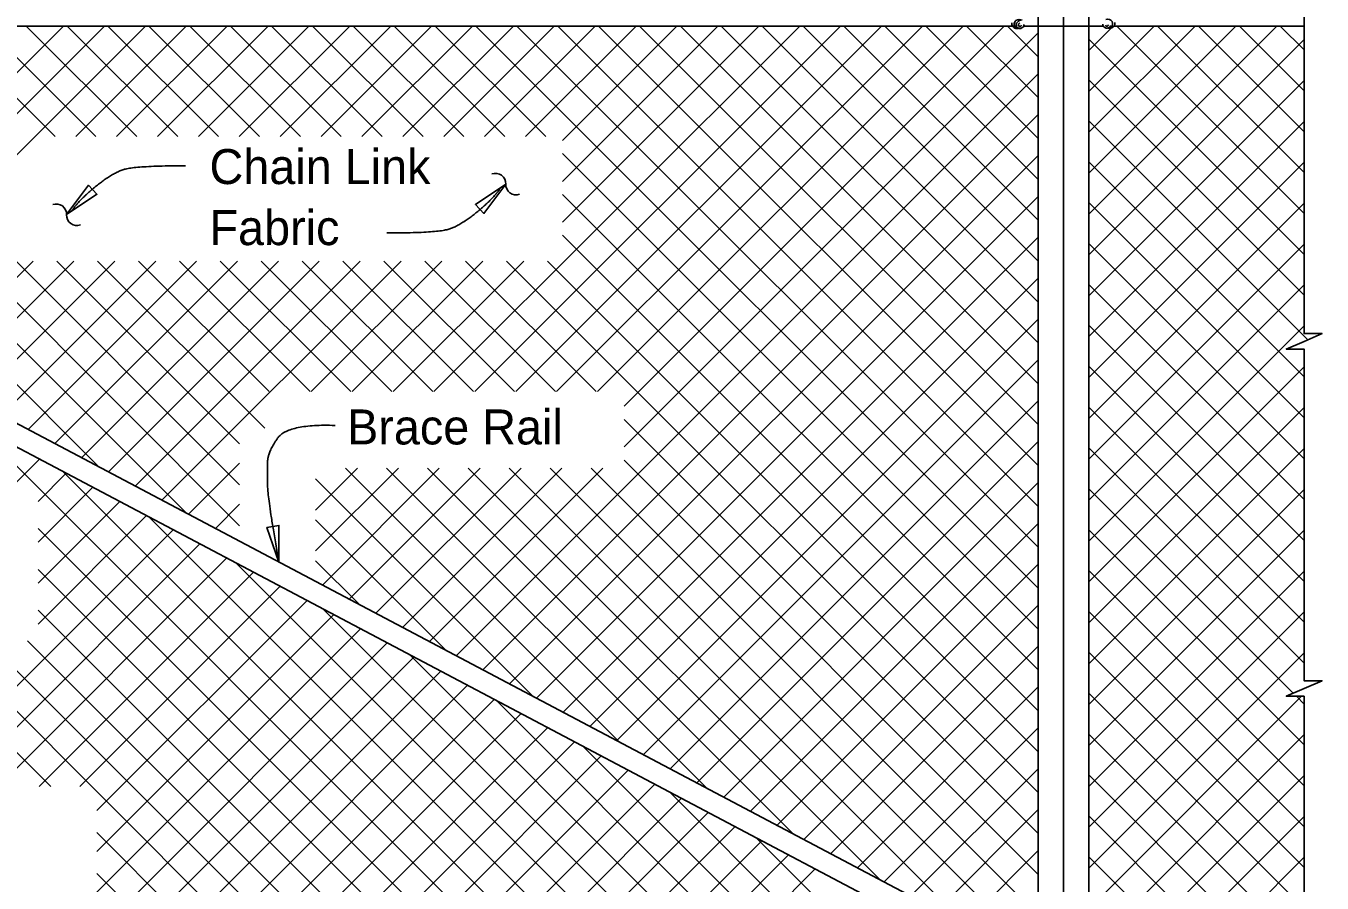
# Model space of a CAD drawing. Extents: x 110698 to 110915, y 110390 to 110472.
# Drawn here: x 110888.85 to 110896.32, y 110461.82 to 110466.76 of the extents above; entities that cross this region are included whole.
import ezdxf

# ---------------------------------------------------------------- set-up
doc = ezdxf.new("R2010")
doc.units = 0
for name, color, linetype in [('AdhocPoint_dp', 7, 'Continuous'), ('Border', 7, 'Continuous'), ('Patterning', 7, 'Continuous'), ('PlotBorder_dp', 7, 'Continuous'), ('SheetBorder_dp', 7, 'Continuous'), ('TextMisc', 7, 'Continuous')]:
    doc.layers.add(name, color=color, linetype=linetype)

msp = doc.modelspace()

# ---------------------------------------------------------------- linework, layer by layer
at = {"layer": 'AdhocPoint_dp'}
msp.add_line((110894.8293, 110469.3136), (110894.8293, 110458.9732), dxfattribs=at)
at = {"layer": 'Patterning'}
msp.add_line((110894.6836, 110466.764), (110894.9752, 110466.764), dxfattribs=at)
at = {"layer": 'PlotBorder_dp'}
for points in [[(110896.2164, 110466.9474), (110896.2164, 110464.9911), (110896.3197, 110464.9911), (110896.2164, 110464.9461), (110896.1131, 110464.9011), (110896.2164, 110464.9011), (110896.2164, 110464.0075)], [(110896.2164, 110464.0075), (110896.2164, 110462.9898), (110896.3197, 110462.9898), (110896.2164, 110462.9448), (110896.1131, 110462.8998), (110896.2164, 110462.8998), (110896.2164, 110460.6954)]]:
    msp.add_lwpolyline(points, dxfattribs=at)
for points in [[(110889.0827, 110465.6766), (110889.2579, 110465.7944), (110889.2093, 110465.8456)], [(110891.6148, 110465.8526), (110891.4396, 110465.7347), (110891.4882, 110465.6836)], [(110890.3071, 110463.6738), (110890.3068, 110463.885), (110890.2373, 110463.8731)]]:
    msp.add_lwpolyline(points, close=True, dxfattribs=at)
for centre, start, end in [((110891.5547, 110465.8554), 357.71778, 109.44499), ((110891.6738, 110465.8507), 177.71778, 289.44499), ((110889.0235, 110465.6785), 357.71778, 109.44499), ((110889.1427, 110465.6737), 177.71778, 289.44499)]:
    msp.add_arc(centre, 0.0596, start, end, dxfattribs=at)
for points in [[(110889.7678, 110465.9582), (110889.4777, 110465.9582), (110889.3411, 110465.9134), (110889.1541, 110465.7598), (110889.1157, 110465.7022)], [(110890.9295, 110465.5709), (110891.2197, 110465.5709), (110891.3563, 110465.6157), (110891.5433, 110465.7693), (110891.5816, 110465.8269)], [(110890.6302, 110464.4616), (110890.3607, 110464.4698), (110890.2426, 110464.3114), (110890.2396, 110464.1902), (110890.2443, 110464.0224), (110890.307, 110463.6737)]]:
    msp.add_open_spline(points, degree=2, dxfattribs=at)
at = {"layer": 'SheetBorder_dp'}
for p, q in [((110886.7285, 110466.764), (110889.2716, 110464.2209)), ((110886.9642, 110466.764), (110889.7714, 110463.9568)), ((110887.1999, 110466.764), (110890.0805, 110463.8834)), ((110887.4356, 110466.764), (110890.0805, 110464.1191)), ((110887.4732, 110465.1713), (110889.0659, 110466.764)), ((110887.6274, 110465.0898), (110889.3016, 110466.764)), ((110887.7816, 110465.0083), (110889.5373, 110466.764)), ((110888.3784, 110466.764), (110889.0161, 110466.1263)), ((110888.6141, 110466.764), (110889.2518, 110466.1263)), ((110888.8498, 110466.764), (110889.4875, 110466.1263)), ((110889.0855, 110466.764), (110889.7232, 110466.1263)), ((110889.1353, 110466.1263), (110889.773, 110466.764)), ((110889.3213, 110466.764), (110889.9589, 110466.1263)), ((110889.371, 110466.1263), (110890.0087, 110466.764)), ((110889.557, 110466.764), (110890.1946, 110466.1263)), ((110889.6067, 110466.1263), (110890.2444, 110466.764)), ((110889.7927, 110466.764), (110890.4303, 110466.1263)), ((110889.8424, 110466.1263), (110890.4801, 110466.764)), ((110890.0284, 110466.764), (110890.666, 110466.1263)), ((110890.0781, 110466.1263), (110890.7158, 110466.764)), ((110890.2641, 110466.764), (110890.9017, 110466.1263)), ((110890.3138, 110466.1263), (110890.9515, 110466.764)), ((110890.4998, 110466.764), (110891.1374, 110466.1263)), ((110890.5495, 110466.1263), (110891.1872, 110466.764)), ((110890.7355, 110466.764), (110891.3731, 110466.1263)), ((110890.7852, 110466.1263), (110891.4229, 110466.764)), ((110890.9712, 110466.764), (110891.6088, 110466.1263)), ((110891.0209, 110466.1263), (110891.6586, 110466.764)), ((110891.2006, 110464.6561), (110893.3085, 110466.764)), ((110891.2069, 110466.764), (110891.8445, 110466.1263)), ((110891.2566, 110466.1263), (110891.8943, 110466.764)), ((110891.4363, 110464.6561), (110893.5442, 110466.764)), ((110891.4426, 110466.764), (110894.6836, 110463.523)), ((110891.4923, 110466.1263), (110892.13, 110466.764)), ((110891.672, 110464.6561), (110893.7799, 110466.764)), ((110891.6783, 110466.764), (110894.6836, 110463.7587)), ((110891.728, 110466.1263), (110892.3657, 110466.764)), ((110891.9077, 110464.6561), (110894.0156, 110466.764)), ((110891.914, 110466.764), (110894.6836, 110463.9944)), ((110891.9415, 110466.1041), (110892.6014, 110466.764)), ((110891.9415, 110465.6327), (110893.0728, 110466.764)), ((110891.9415, 110465.8684), (110892.8371, 110466.764)), ((110892.1434, 110464.6561), (110894.2513, 110466.764)), ((110892.1434, 110464.6561), (110894.2513, 110466.764)), ((110892.1497, 110466.764), (110894.6836, 110464.2301)), ((110892.2962, 110464.5732), (110894.487, 110466.764)), ((110892.2962, 110464.3375), (110894.6836, 110466.7248)), ((110892.3854, 110466.764), (110894.6836, 110464.4658)), ((110892.6211, 110466.764), (110894.6836, 110464.7015)), ((110892.8568, 110466.764), (110894.6836, 110464.9372)), ((110893.0925, 110466.764), (110894.6836, 110465.1729)), ((110893.3282, 110466.764), (110894.6836, 110465.4086)), ((110893.5639, 110466.764), (110894.6836, 110465.6443)), ((110893.7996, 110466.764), (110894.6836, 110465.88)), ((110894.0353, 110466.764), (110894.6836, 110466.1157)), ((110894.271, 110466.764), (110894.6836, 110466.3514)), ((110894.5067, 110466.764), (110894.6836, 110466.5871)), ((110894.9752, 110465.6803), (110896.0589, 110466.764)), ((110894.9752, 110466.1517), (110895.5875, 110466.764)), ((110894.9752, 110466.3874), (110895.3518, 110466.764)), ((110894.9752, 110466.6231), (110895.1047, 110466.7526)), ((110894.9797, 110465.9204), (110895.8232, 110466.764)), ((110895.1358, 110466.764), (110896.2163, 110465.6834)), ((110895.3715, 110466.764), (110896.2163, 110465.9191)), ((110895.6072, 110466.764), (110896.2163, 110466.1548)), ((110895.8429, 110466.764), (110896.2163, 110466.3905)), ((110896.0786, 110466.764), (110896.2163, 110466.6262)), ((110894.9752, 110466.6888), (110896.2163, 110465.4477)), ((110894.9752, 110465.4446), (110896.2163, 110466.6857)), ((110891.3284, 110463.134), (110894.6836, 110466.4891)), ((110894.9752, 110466.4531), (110896.2163, 110465.212)), ((110894.9752, 110465.2089), (110896.2163, 110466.45)), ((110891.4826, 110463.0525), (110894.6836, 110466.2534)), ((110894.9752, 110466.2174), (110896.2374, 110464.9553)), ((110894.9752, 110464.9732), (110896.2163, 110466.2143)), ((110891.9415, 110466.0293), (110894.6836, 110463.2873)), ((110891.6368, 110462.971), (110894.6836, 110466.0177)), ((110894.9752, 110465.9817), (110896.2163, 110464.7406)), ((110894.9752, 110464.7375), (110896.2163, 110465.9786)), ((110891.791, 110462.8895), (110894.6836, 110465.782)), ((110891.9415, 110465.7936), (110894.6836, 110463.0516)), ((110894.9752, 110465.746), (110896.2163, 110464.5049)), ((110894.9752, 110464.5018), (110896.2163, 110465.7429)), ((110891.9415, 110465.5579), (110894.6836, 110462.8159)), ((110891.9453, 110462.808), (110894.6836, 110465.5463)), ((110894.9752, 110465.5103), (110896.2163, 110464.2692)), ((110894.9752, 110464.2661), (110896.2163, 110465.5071)), ((110888.2442, 110464.7638), (110888.8896, 110465.4092)), ((110888.3984, 110464.6823), (110889.1253, 110465.4092)), ((110888.3984, 110464.6823), (110889.1253, 110465.4092)), ((110888.5526, 110464.6008), (110889.361, 110465.4092)), ((110888.5526, 110464.6008), (110889.361, 110465.4092)), ((110888.7069, 110464.5193), (110889.5967, 110465.4092)), ((110888.7069, 110464.5193), (110889.5967, 110465.4092)), ((110888.8611, 110464.4378), (110889.8325, 110465.4092)), ((110888.8611, 110464.4378), (110889.8325, 110465.4092)), ((110889.0153, 110464.3563), (110890.0682, 110465.4092)), ((110889.0261, 110465.4092), (110890.0805, 110464.3548)), ((110889.1695, 110464.2749), (110890.3039, 110465.4092)), ((110889.2618, 110465.4092), (110890.2249, 110464.4461)), ((110889.3237, 110464.1934), (110890.5396, 110465.4092)), ((110889.4779, 110464.1119), (110890.7753, 110465.4092)), ((110889.4975, 110465.4092), (110890.2506, 110464.6561)), ((110889.4975, 110465.4092), (110890.2506, 110464.6561)), ((110889.6321, 110464.0304), (110891.011, 110465.4092)), ((110889.7332, 110465.4092), (110890.4863, 110464.6561)), ((110889.9689, 110465.4092), (110890.722, 110464.6561)), ((110889.9689, 110465.4092), (110890.722, 110464.6561)), ((110889.9689, 110465.4092), (110890.722, 110464.6561)), ((110890.2046, 110465.4092), (110890.9577, 110464.6561)), ((110890.2046, 110465.4092), (110890.9577, 110464.6561)), ((110890.4403, 110465.4092), (110891.1934, 110464.6561)), ((110890.4935, 110464.6561), (110891.2467, 110465.4092)), ((110890.676, 110465.4092), (110891.4291, 110464.6561)), ((110890.7292, 110464.6561), (110891.4824, 110465.4092)), ((110890.9117, 110465.4092), (110891.6648, 110464.6561)), ((110890.9649, 110464.6561), (110891.7181, 110465.4092)), ((110891.1474, 110465.4092), (110891.9005, 110464.6561)), ((110891.3831, 110465.4092), (110892.1362, 110464.6561)), ((110891.6188, 110465.4092), (110894.6836, 110462.3445)), ((110891.8545, 110465.4092), (110894.6836, 110462.5802)), ((110892.0995, 110462.7265), (110894.6836, 110465.3106)), ((110894.9752, 110465.2746), (110896.2163, 110464.0335)), ((110894.9752, 110464.0304), (110896.2163, 110465.2714)), ((110892.2537, 110462.645), (110894.6836, 110465.0749)), ((110894.9752, 110465.0389), (110896.2163, 110463.7978)), ((110894.9752, 110463.7947), (110896.2163, 110465.0357)), ((110892.4079, 110462.5635), (110894.6836, 110464.8392)), ((110894.9752, 110464.8032), (110896.2163, 110463.5621)), ((110894.9752, 110463.559), (110896.2163, 110464.8)), ((110892.5621, 110462.482), (110894.6836, 110464.6035)), ((110894.9752, 110464.5675), (110896.2163, 110463.3264)), ((110894.9752, 110463.3233), (110896.2163, 110464.5643)), ((110888.5595, 110464.4616), (110891.8943, 110461.1268)), ((110892.2962, 110464.4961), (110894.6836, 110462.1088)), ((110892.7163, 110462.4005), (110894.6836, 110464.3678)), ((110894.9752, 110464.3318), (110896.2163, 110463.0907)), ((110894.9752, 110463.0875), (110896.2163, 110464.3286)), ((110888.7132, 110464.0543), (110888.9266, 110464.2676)), ((110889.7863, 110463.9489), (110890.0805, 110464.243)), ((110892.2962, 110464.2604), (110894.6836, 110461.8731)), ((110888.9184, 110464.0237), (110889.0808, 110464.1861)), ((110889.0593, 110464.1975), (110892.13, 110461.1268)), ((110890.518, 110463.7377), (110890.9954, 110464.2152)), ((110890.518, 110463.9734), (110890.7597, 110464.2152)), ((110890.518, 110464.153), (110891.7708, 110462.9002)), ((110890.5574, 110463.5414), (110891.2311, 110464.2152)), ((110890.6915, 110464.2152), (110892.2707, 110462.636)), ((110890.6915, 110464.2152), (110892.2707, 110462.636)), ((110890.7116, 110463.4599), (110891.4668, 110464.2152)), ((110890.8658, 110463.3784), (110891.7025, 110464.2152)), ((110890.8658, 110463.3784), (110891.7025, 110464.2152)), ((110890.9272, 110464.2152), (110892.7705, 110462.3719)), ((110891.02, 110463.2969), (110891.9382, 110464.2152)), ((110891.1629, 110464.2152), (110893.2704, 110462.1077)), ((110891.1629, 110464.2152), (110893.2704, 110462.1077)), ((110891.1629, 110464.2152), (110893.2704, 110462.1077)), ((110891.1742, 110463.2154), (110892.1739, 110464.2152)), ((110891.3986, 110464.2152), (110893.7702, 110461.8436)), ((110891.3986, 110464.2152), (110893.7702, 110461.8436)), ((110891.6343, 110464.2152), (110894.2701, 110461.5794)), ((110891.87, 110464.2152), (110894.6836, 110461.4017)), ((110892.1057, 110464.2152), (110894.6836, 110461.6374)), ((110888.9184, 110463.788), (110889.235, 110464.1046)), ((110892.8705, 110462.319), (110894.6836, 110464.1321)), ((110894.9752, 110464.0961), (110896.1538, 110462.9175)), ((110894.9752, 110462.8518), (110896.2163, 110464.0929)), ((110888.9184, 110463.5523), (110889.3892, 110464.0232)), ((110889.9405, 110463.8674), (110890.0805, 110464.0073)), ((110888.9184, 110463.3166), (110889.5434, 110463.9417)), ((110889.5591, 110463.9333), (110892.3657, 110461.1268)), ((110888.2168, 110462.3794), (110889.6976, 110463.8602)), ((110888.9184, 110463.867), (110891.6586, 110461.1268)), ((110890.518, 110463.9173), (110891.271, 110463.1643)), ((110893.0247, 110462.2375), (110894.6836, 110463.8964)), ((110894.9752, 110463.8604), (110896.2163, 110462.6193)), ((110894.9752, 110462.6161), (110896.2163, 110463.8572)), ((110888.4525, 110462.3794), (110889.8518, 110463.7787)), ((110888.6882, 110462.3794), (110890.006, 110463.6972)), ((110888.9184, 110463.6313), (110891.4229, 110461.1268)), ((110890.059, 110463.6692), (110892.6014, 110461.1268)), ((110890.518, 110463.6816), (110890.7711, 110463.4285)), ((110893.1789, 110462.156), (110894.6836, 110463.6607)), ((110888.9239, 110462.3794), (110890.1602, 110463.6157)), ((110894.9752, 110463.6247), (110896.2163, 110462.3836)), ((110894.9752, 110462.3804), (110896.2163, 110463.6215)), ((110889.1596, 110462.3794), (110890.3145, 110463.5342)), ((110889.257, 110462.2411), (110890.4687, 110463.4527)), ((110890.5588, 110463.4051), (110892.8371, 110461.1268)), ((110893.3331, 110462.0745), (110894.6836, 110463.425)), ((110888.9184, 110463.3956), (110891.1872, 110461.1268)), ((110889.257, 110462.0054), (110890.6229, 110463.3712)), ((110894.9752, 110463.389), (110896.2163, 110462.1479)), ((110894.9752, 110462.1447), (110896.2163, 110463.3858)), ((110889.257, 110461.7697), (110890.7771, 110463.2897)), ((110888.151, 110463.2202), (110888.9918, 110462.3794)), ((110888.3867, 110463.2202), (110890.4801, 110461.1268)), ((110888.6224, 110463.2202), (110890.7158, 110461.1268)), ((110888.8498, 110461.1268), (110890.9313, 110463.2082)), ((110888.8581, 110463.2202), (110890.9515, 110461.1268)), ((110893.4873, 110461.9931), (110894.6836, 110463.1893)), ((110889.0855, 110461.1268), (110891.0855, 110463.1267)), ((110891.0586, 110463.1409), (110893.0728, 110461.1268)), ((110894.9752, 110463.1533), (110896.2163, 110461.9122)), ((110894.9752, 110461.909), (110896.2163, 110463.1501)), ((110889.3213, 110461.1268), (110891.2397, 110463.0453)), ((110889.557, 110461.1268), (110891.3939, 110462.9638)), ((110889.7927, 110461.1268), (110891.5481, 110462.8823)), ((110893.6416, 110461.9116), (110894.6836, 110462.9536)), ((110894.9752, 110462.9176), (110896.2163, 110461.6765)), ((110894.9752, 110461.6733), (110896.2016, 110462.8997)), ((110896.1716, 110462.8997), (110896.2163, 110462.855)), ((110891.5585, 110462.8768), (110893.3085, 110461.1268)), ((110890.0284, 110461.1268), (110891.7023, 110462.8008)), ((110890.2641, 110461.1268), (110891.8566, 110462.7193)), ((110893.7958, 110461.8301), (110894.6836, 110462.7179)), ((110894.9752, 110462.6819), (110896.2163, 110461.4408)), ((110894.9752, 110461.4376), (110896.2163, 110462.6787)), ((110890.4998, 110461.1268), (110892.0108, 110462.6378)), ((110892.0583, 110462.6127), (110893.5442, 110461.1268)), ((110890.7355, 110461.1268), (110892.165, 110462.5563)), ((110890.9712, 110461.1268), (110892.3192, 110462.4748)), ((110893.95, 110461.7486), (110894.6836, 110462.4822)), ((110894.9752, 110462.4462), (110896.2163, 110461.2051)), ((110894.9752, 110461.2019), (110896.2163, 110462.443)), ((110891.2069, 110461.1268), (110892.4734, 110462.3933)), ((110891.4426, 110461.1268), (110892.6276, 110462.3118)), ((110892.5582, 110462.3485), (110893.7799, 110461.1268)), ((110891.6783, 110461.1268), (110892.7818, 110462.2303)), ((110894.1042, 110461.6671), (110894.6836, 110462.2464)), ((110894.9752, 110462.2105), (110896.0589, 110461.1268)), ((110891.914, 110461.1268), (110892.936, 110462.1488)), ((110895.1446, 110461.1357), (110896.2163, 110462.2073)), ((110889.257, 110462.1141), (110890.2444, 110461.1268)), ((110892.1497, 110461.1268), (110893.0902, 110462.0674)), ((110893.058, 110462.0844), (110894.0156, 110461.1268)), ((110892.3854, 110461.1268), (110893.2445, 110461.9859)), ((110894.2584, 110461.5856), (110894.6836, 110462.0107)), ((110894.9752, 110461.9748), (110895.8232, 110461.1268)), ((110895.3715, 110461.1268), (110896.2163, 110461.9716)), ((110889.257, 110461.8784), (110890.0087, 110461.1268)), ((110892.6211, 110461.1268), (110893.3987, 110461.9044))]:
    msp.add_line(p, q, dxfattribs=at)
at = {"layer": 'TextMisc'}
for p, q in [((110894.6836, 110461.3401), (110894.6836, 110466.9853)), ((110894.9752, 110461.3401), (110894.9752, 110466.9853)), ((110886.0734, 110466.764), (110894.535, 110466.764)), ((110894.5999, 110466.764), (110894.6836, 110466.764)), ((110894.9752, 110466.764), (110895.0583, 110466.764)), ((110895.1211, 110466.764), (110896.2163, 110466.764)), ((110894.482, 110461.4674), (110885.2324, 110466.3554)), ((110894.426, 110461.3615), (110885.1764, 110466.2494))]:
    msp.add_line(p, q, dxfattribs=at)
for centre, major_axis, ratio, start_param, end_param in [((110894.5563, 110466.7764), (-0.0249, 0), 0.957868, 6.009018, 7.089857), ((110894.5739, 110466.7735), (0.0295, 0), 0.957868, 1.220941, 4.039556), ((110894.5874, 110466.7753), (-0.0303, -0.0108), 0.724765, 4.35367, 6.324556), ((110894.5772, 110466.7667), (0.0206, -0.0021), 0.798607, 3.333154, 5.220153), ((110894.584, 110466.7712), (-0.0139, 0), 0.957868, 5.22362, 6.905413), ((110894.5784, 110466.7689), (-0.00795, 0), 0.957868, 6.140374, 9.314262), ((110894.5769, 110466.7734), (0.0251, 0), 0.957868, 5.531357, 6.227833), ((110895.0804, 110466.7752), (-0.0251, 0), 0.957868, 0.055352, 0.751829), ((110895.079, 110466.7706), (0.00795, 0), 0.957868, 3.252108, 6.425997), ((110895.0801, 110466.7685), (-0.0206, -0.0021), 0.798607, 1.063032, 2.950031), ((110895.0835, 110466.7753), (-0.0295, 0), 0.957868, 2.243629, 5.062245), ((110895.1011, 110466.7782), (0.0249, 0), 0.957868, 5.476514, 6.557353), ((110894.5577, 110466.7724), (0.0231, 0), 0.957868, 3.779554, 4.879821), ((110894.5638, 110466.7667), (0.0206, -0.0021), 0.798607, 4.32653, 5.220153), ((110894.5698, 110466.7855), (0.0391, 0), 0.957868, 5.082588, 5.41974), ((110895.0875, 110466.7872), (-0.0391, 0), 0.957868, 0.863445, 1.200597), ((110895.0936, 110466.7685), (-0.0206, -0.0021), 0.798607, 1.063032, 1.956656), ((110895.0997, 110466.7742), (-0.0231, 0), 0.957868, 1.403365, 2.503632)]:
    msp.add_ellipse(centre, major_axis=major_axis, ratio=ratio, start_param=start_param, end_param=end_param, dxfattribs=at)

# ---------------------------------------------------------------- texts
at = {"layer": 'Border'}
msp.add_text('Brace Rail', height=0.2016, dxfattribs=at).set_placement((110890.6997, 110464.3518))
at = {"layer": 'PlotBorder_dp'}
for s, p in [('Chain Link ', (110889.9066, 110465.8529)), ('Fabric ', (110889.9066, 110465.5009))]:
    msp.add_text(s, height=0.2016, dxfattribs=at).set_placement(p)

doc.saveas('drawing.dxf')
